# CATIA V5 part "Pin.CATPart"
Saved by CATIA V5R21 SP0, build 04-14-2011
Part number: Pin
Bounding box of the stored display mesh (mm): x -10.997 to 10.997, y 0 to 38, z -10.885 to 10.885
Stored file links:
  D:\CATIA V5R21 E-RESOURCES\CATIA-V5R21\catia-v5r21-Prts\c12_catia_v5r21_prt\c12_catia_v5r21figr_12-53\Pin.CATPart
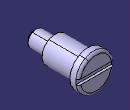
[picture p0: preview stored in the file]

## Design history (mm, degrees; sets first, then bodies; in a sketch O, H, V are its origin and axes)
Body1 (main body)
  Sketch1 on yz-plane, origin (0, 0, 0), H (0, 1, 0), V (0, 0, 1)
    line L1 (0, 0) -> (0, 5)
    line L2 (0, 5) -> (13, 5)
    line L3 (13, 5) -> (13, 8)
    line L4 (13, 8) -> (33, 8)
    line L5 (33, 8) -> (33, 11)
    line L6 (33, 11) -> (38, 11)
    line L7 (38, 11) -> (38, 0)
    point P7 (38, 0)
    line L8 (38, 0) -> (0, 0)
    distance L8 L6 = 11
    distance L4 L8 = 8
    length L8 = 38
    distance L2 L8 = 5
    length L6 = 5
    length L4 = 20
    vertical: L1 V, L3 V, L5 V, L7 V
    horizontal: L2 H, L4 H, L8 H, L6 H
    coincidence: P7 H
  Shaft1: profile Sketch1, axis edge of Sketch1, angle 360
  Chamfer1: length 1.5, angle 45, on 1 edge
  Fillet1: radius 1.5, on 1 edge
  Sketch2 on face of Shaft1, origin (0, 38, 0), H (-1, 0, 0), V (0, 0, 1)
    line L1 (-15.6575, 1.5) -> (20.3727, 1.5)
    line L2 (20.3727, 1.5) -> (20.3727, -1.5)
    line L3 (20.3727, -1.5) -> (-15.6575, -1.5)
    line L4 (-15.6575, -1.5) -> (-15.6575, 1.5)
    distance H L3 = 1.5
    length L4 = 3
    horizontal: L1 H, L3 H
    vertical: L2 V, L4 V
  Pocket1: profile Sketch2, direction (0, -1, 0), length 1.5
